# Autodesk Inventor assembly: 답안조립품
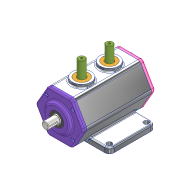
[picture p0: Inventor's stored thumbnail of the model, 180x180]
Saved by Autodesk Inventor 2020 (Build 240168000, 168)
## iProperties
Created: 2021-06
Part Number: 답안조립품
Document SubType Name: Assembly
Designer: MIRAE
Author: MIRAE
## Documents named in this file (11)
- C:\Users\MIRAE\Desktop\710606V1008\답안조립품.iam
- C:\Users\MIRAE\Desktop\710606V1008\본체.ipt
- C:\Users\MIRAE\Desktop\710606V1008\베어링 6203.ipt
- C:\Users\MIRAE\Desktop\710606V1008\앞커버.ipt
- C:\Users\MIRAE\Desktop\710606V1008\오일실.ipt
- C:\Users\MIRAE\Desktop\710606V1008\편심축.ipt
- C:\Users\MIRAE\Desktop\710606V1008\볼트 M4.ipt
- C:\Users\MIRAE\Desktop\710606V1008\뒷커버.ipt
- C:\Users\MIRAE\Desktop\710606V1008\베어링 6302.ipt
- C:\Users\MIRAE\Desktop\710606V1008\부시.ipt
- C:\Users\MIRAE\Desktop\710606V1008\슬라이더.ipt
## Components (10 placed, 3 different names)
1. 7-베어링 6203:1
2. 8-오일실:1
3. 9-M4-소켓머리:1
4. 9-M4-소켓머리:2
5. 9-M4-소켓머리:3
6. 9-M4-소켓머리:4
7. 9-M4-소켓머리:5
8. 9-M4-소켓머리:6
9. 9-M4-소켓머리:7
10. 9-M4-소켓머리:8
